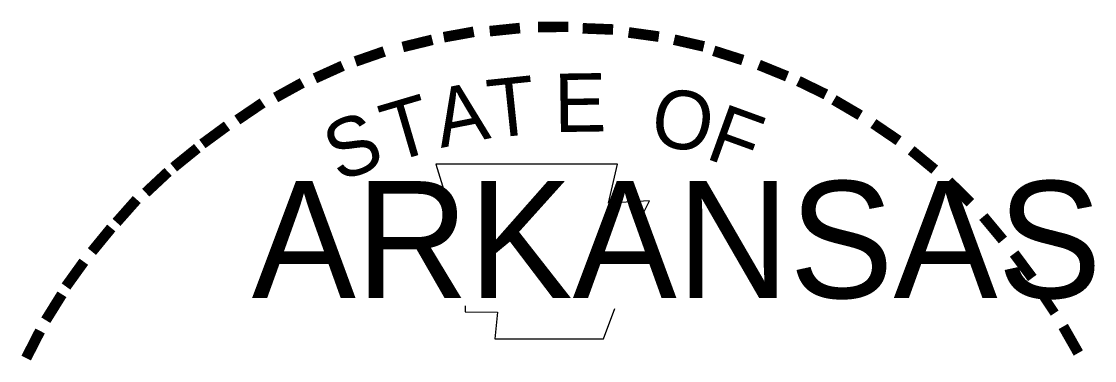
# Model space of a CAD drawing. Extents: x 6028666 to 6031787, y 5366484 to 5368484.
# Drawn here: x 6031369.8 to 6031643.8, y 5366958.9 to 5367045.3 of the extents above; entities that cross this region are included whole.
import ezdxf

# ---------------------------------------------------------------- set-up
doc = ezdxf.new("R2010")
doc.units = 0
doc.layers.add('Level 49', color=7, linetype='Continuous')

msp = doc.modelspace()

# ---------------------------------------------------------------- linework, layer by layer
at = {"layer": 'Level 49'}
for points in [[(6031475.62, 5367008.95), (6031479.38, 5366996.47)], [(6031527.96, 5366995.15), (6031530.13, 5366999.58), (6031519.65, 5366998.96), (6031521.97, 5367008.91), (6031475.62, 5367008.95)], [(6031483.04, 5366972.77), (6031483.05, 5366971.3), (6031491.33, 5366971.17), (6031490.64, 5366964.36), (6031518.42, 5366964.37), (6031521.31, 5366972.11)]]:
    msp.add_lwpolyline(points, dxfattribs=at)

# ---------------------------------------------------------------- texts
for s, height, rotation, p in [('-', 23.84, 0.1862, (6031500.27, 5367034.69)), ('-', 23.84, 10.2193, (6031477.85, 5367031.96)), ('-', 23.84, 5.8968, (6031488.88, 5367033.51)), ('-', 23.84, 357.743, (6031511.31, 5367034.4)), ('-', 23.84, 352.1617, (6031522.17, 5367033.56)), ('-', 23.84, 13.6302, (6031467.93, 5367029.5)), ('-', 23.84, 347.2049, (6031533.03, 5367031.98)), ('-', 23.84, 19.1761, (6031456.74, 5367025.93)), ('-', 23.84, 342.3362, (6031542.43, 5367029.47)), ('-', 23.84, 24.3072, (6031447.2, 5367021.82)), ('-', 23.84, 337.8551, (6031553.31, 5367026.23)), ('T', 14.9, 6.0228, (6031489.55, 5367015.49)), ('E', 14.9, 0.8323, (6031505.91, 5367017.07)), ('-', 23.84, 28.7918, (6031437.85, 5367017.15)), ('A', 14.9, 11.2132, (6031476.88, 5367013.01)), ('-', 23.84, 334.1211, (6031562.9, 5367022.43)), ('T', 14.9, 16.4036, (6031464.4, 5367009.24)), ('O', 14.9, 350.4515, (6031529.85, 5367014.11)), ('-', 23.84, 329.6409, (6031571.39, 5367018.08)), ('-', 23.84, 34.0636, (6031428.88, 5367011.76)), ('F', 14.9, 340.0707, (6031544.04, 5367010.53)), ('S', 14.9, 21.594, (6031450.82, 5367004.18)), ('-', 23.84, 36.2317, (6031420.27, 5367005.81)), ('-', 23.84, 325.8627, (6031581, 5367012.44)), ('-', 23.84, 38.9507, (6031413.32, 5367000.06)), ('-', 23.84, 320.5297, (6031590.05, 5367006.25)), ('-', 23.84, 42.9622, (6031406.74, 5366993.94)), ('-', 23.84, 315.5786, (6031599.12, 5366998.96)), ('-', 23.84, 48.4231, (6031399.99, 5366986.91)), ('-', 23.84, 309.8797, (6031607.45, 5366990.74)), ('-', 23.84, 50.6142, (6031393.97, 5366979.69)), ('-', 23.84, 54.2325, (6031387.77, 5366971.19)), ('-', 23.84, 306.6522, (6031615.05, 5366981.78)), ('-', 20.86, 303.6753, (6031622.47, 5366973.18)), ('-', 23.84, 58.0706, (6031383.04, 5366963.06)), ('-', 23.84, 62.8714, (6031378.51, 5366954.01)), ('-', 23.84, 299.6684, (6031627.13, 5366964.2))]:
    msp.add_text(s, height=height, rotation=rotation, dxfattribs=at).set_placement(p)
msp.add_text('ARKANSAS', height=29.805, dxfattribs=at).set_placement((6031428.58, 5366974.78))

doc.saveas('drawing.dxf')
